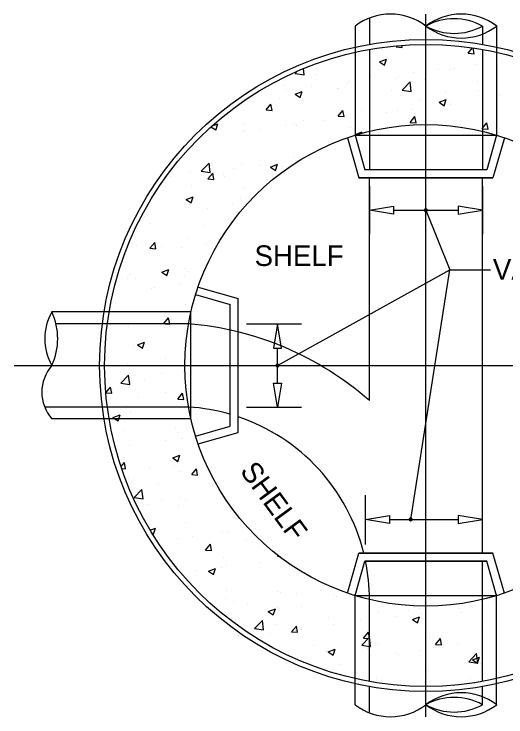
# Model space of a CAD drawing. Extents: x 6712067 to 6713867, y 1867712 to 1869162.
# Drawn here: x 6712515.6 to 6712658.4, y 1867920 to 1868124.2 of the extents above; entities that cross this region are included whole.
import ezdxf

# ---------------------------------------------------------------- set-up
doc = ezdxf.new("R2010")
doc.units = 0
for name, color, linetype in [('G-MARK', 7, 'Continuous'), ('G-TEXT', 7, 'Continuous'), ('Misc CnstDet(22)', 7, 'Continuous')]:
    doc.layers.add(name, color=color, linetype=linetype)

msp = doc.modelspace()

# ---------------------------------------------------------------- linework, layer by layer
at = {"layer": 'G-MARK'}
for p, q in [((6712625.76, 1868067.25), (6712644.59, 1868067.25)), ((6712635.18, 1868067.25), (6712642.18, 1868049.91)), ((6712630.8, 1867977.41), (6712642.18, 1868049.91)), ((6712583.12, 1868034.19), (6712599.1, 1868034.19)), ((6712592.12, 1868017), (6712592.12, 1868027.19)), ((6712583.12, 1868010), (6712599.1, 1868010)), ((6712617.66, 1867970.09), (6712617.66, 1867984.4)), ((6712624.65, 1867977.41), (6712644.59, 1867977.41))]:
    msp.add_line(p, q, dxfattribs=at)
msp.add_lwpolyline([(6712592.12, 1868022.15), (6712642.18, 1868049.91), (6712653.98, 1868049.91)], dxfattribs=at)
at = {"layer": 'G-TEXT'}
for points in [[(6712625.76, 1868068.42), (6712625.76, 1868066.1), (6712618.77, 1868067.25)], [(6712644.59, 1868068.42), (6712644.59, 1868066.1), (6712651.58, 1868067.25)], [(6712590.94, 1868027.19), (6712593.27, 1868027.19), (6712592.12, 1868034.19)], [(6712590.94, 1868017), (6712593.27, 1868017), (6712592.12, 1868010)], [(6712624.65, 1867978.57), (6712624.65, 1867976.24), (6712617.66, 1867977.41)], [(6712644.59, 1867978.57), (6712644.59, 1867976.24), (6712651.58, 1867977.41)]]:
    msp.add_lwpolyline(points, close=True, dxfattribs=at)
at = {"layer": 'Misc CnstDet(22)'}
for p, q in [((6712618.78, 1868123.07), (6712618.78, 1868115.45)), ((6712635.18, 1867920.01), (6712635.18, 1868124.24)), ((6712614.62, 1868120.74), (6712614.62, 1868114.69)), ((6712651.59, 1868120.74), (6712651.59, 1868115.45)), ((6712655.74, 1868120.74), (6712655.74, 1868114.45)), ((6712614.62, 1868114.62), (6712614.62, 1868089.01)), ((6712626.53, 1868114.68), (6712626.86, 1868115.05)), ((6712626.53, 1868114.68), (6712628.28, 1868114.52)), ((6712628.28, 1868114.52), (6712628.16, 1868115.16)), ((6712647.44, 1868112.85), (6712648.77, 1868114.43)), ((6712649.19, 1868112.7), (6712648.87, 1868114.42)), ((6712655.74, 1868114.62), (6712655.74, 1868089.01)), ((6712618.78, 1868113.97), (6712618.78, 1868089.01)), ((6712647.44, 1868112.85), (6712649.19, 1868112.7)), ((6712651.59, 1868113.97), (6712651.59, 1868089.01)), ((6712621.68, 1868110.33), (6712623.72, 1868111.12)), ((6712621.68, 1868110.33), (6712623.13, 1868109.36)), ((6712623.13, 1868109.36), (6712623.72, 1868111.11)), ((6712657.29, 1868110.19), (6712657.29, 1868110.19)), ((6712599.81, 1868106.57), (6712599.6, 1868108.37)), ((6712638.84, 1868108.12), (6712638.84, 1868108.12)), ((6712642.32, 1868108.14), (6712642.32, 1868108.14)), ((6712643.55, 1868108.35), (6712643.55, 1868108.35)), ((6712649.88, 1868109.56), (6712649.88, 1868109.56)), ((6712597.21, 1868106.97), (6712597.84, 1868107.62)), ((6712597.21, 1868106.97), (6712599.81, 1868106.57)), ((6712603.54, 1868106.64), (6712603.54, 1868106.64)), ((6712631.54, 1868107.15), (6712631.54, 1868107.15)), ((6712612.46, 1868104.09), (6712612.46, 1868104.09)), ((6712613.13, 1868104.73), (6712613.13, 1868104.73)), ((6712619.09, 1868105.98), (6712619.09, 1868105.98)), ((6712626.56, 1868105.42), (6712626.56, 1868105.42)), ((6712627.19, 1868105.96), (6712627.19, 1868105.96)), ((6712628.32, 1868102.15), (6712630.6, 1868104.51)), ((6712630.92, 1868101.74), (6712630.6, 1868104.51)), ((6712634.65, 1868105.33), (6712634.65, 1868105.33)), ((6712650.21, 1868104.66), (6712650.21, 1868104.66)), ((6712594.11, 1868103.38), (6712594.11, 1868103.38)), ((6712594.79, 1868102.31), (6712594.79, 1868102.31)), ((6712597.5, 1868102.04), (6712597.5, 1868102.04)), ((6712602.09, 1868103.27), (6712602.09, 1868103.27)), ((6712609.55, 1868102.51), (6712609.55, 1868102.51)), ((6712609.68, 1868102.72), (6712609.68, 1868102.72)), ((6712625.24, 1868102.07), (6712625.24, 1868102.07)), ((6712628.32, 1868102.15), (6712630.92, 1868101.74)), ((6712650.54, 1868101.94), (6712650.54, 1868101.94)), ((6712597.19, 1868100.93), (6712599.22, 1868101.71)), ((6712597.19, 1868100.93), (6712598.64, 1868099.96)), ((6712598.64, 1868099.96), (6712599.22, 1868101.71)), ((6712640.8, 1868101.4), (6712640.8, 1868101.4)), ((6712656.36, 1868100.75), (6712656.36, 1868100.75)), ((6712656.93, 1868100.5), (6712656.93, 1868100.5)), ((6712588.77, 1868096.41), (6712590.17, 1868098.09)), ((6712590.51, 1868096.25), (6712590.17, 1868098.08)), ((6712592.55, 1868099.59), (6712592.55, 1868099.59)), ((6712633.53, 1868099.03), (6712633.53, 1868099.03)), ((6712639.08, 1868098.6), (6712641.12, 1868099.38)), ((6712639.08, 1868098.6), (6712640.52, 1868097.62)), ((6712640.52, 1868097.62), (6712641.12, 1868099.38)), ((6712641.97, 1868098.44), (6712641.97, 1868098.44)), ((6712642.2, 1868098.08), (6712642.2, 1868098.08)), ((6712588.77, 1868096.41), (6712590.51, 1868096.25)), ((6712609.68, 1868094.58), (6712611.08, 1868096.25)), ((6712611.42, 1868094.43), (6712611.08, 1868096.25)), ((6712616.54, 1868096.1), (6712616.54, 1868096.1)), ((6712626.83, 1868096.25), (6712626.83, 1868096.25)), ((6712631.16, 1868096.62), (6712631.16, 1868096.62)), ((6712609.68, 1868094.58), (6712611.42, 1868094.43)), ((6712612.11, 1868094.39), (6712612.11, 1868094.39)), ((6712623.87, 1868095.65), (6712623.87, 1868095.65)), ((6712630.58, 1868092.75), (6712631.98, 1868094.43)), ((6712632.32, 1868092.59), (6712631.98, 1868094.43)), ((6712572.95, 1868091.63), (6712574.73, 1868092.32)), ((6712574.15, 1868090.55), (6712574.73, 1868092.32)), ((6712582.17, 1868092.48), (6712582.17, 1868092.48)), ((6712594.41, 1868091.78), (6712594.41, 1868091.78)), ((6712597.14, 1868092.34), (6712597.14, 1868092.34)), ((6712597.73, 1868091.82), (6712597.73, 1868091.82)), ((6712599.54, 1868093.19), (6712599.54, 1868093.19)), ((6712605.45, 1868093.23), (6712605.45, 1868093.23)), ((6712630.58, 1868092.75), (6712632.33, 1868092.6)), ((6712651.59, 1868091.04), (6712652.89, 1868092.59)), ((6712653.23, 1868090.77), (6712652.89, 1868092.59)), ((6712572.78, 1868091.48), (6712574.15, 1868090.56)), ((6712582.01, 1868090.15), (6712582.01, 1868090.15)), ((6712582.53, 1868090.27), (6712582.53, 1868090.27)), ((6712587.13, 1868090.82), (6712587.13, 1868090.82)), ((6712613.29, 1868091.17), (6712613.29, 1868091.17)), ((6712614.62, 1868089.21), (6712616.63, 1868089.99)), ((6712616.48, 1868089.56), (6712616.63, 1868089.97)), ((6712651.49, 1868090.93), (6712651.59, 1868091.04)), ((6712651.49, 1868090.93), (6712651.59, 1868090.92)), ((6712651.59, 1868090.92), (6712653.23, 1868090.77)), ((6712656.59, 1868090.79), (6712656.59, 1868090.79)), ((6712612.4, 1868088.29), (6712615.72, 1868076.66)), ((6712614.59, 1868089.19), (6712614.62, 1868089.21)), ((6712614.59, 1868089.19), (6712614.62, 1868089.17)), ((6712614.62, 1868089.17), (6712614.78, 1868089.07)), ((6712614.62, 1868089.01), (6712617.48, 1868078.99)), ((6712614.62, 1868089.01), (6712655.74, 1868089.01)), ((6712618.78, 1868089.01), (6712618.78, 1868078.99)), ((6712651.59, 1868089.01), (6712651.59, 1868078.99)), ((6712655.74, 1868089.01), (6712652.88, 1868078.99)), ((6712655.74, 1868089.01), (6712652.88, 1868078.99)), ((6712657.97, 1868088.29), (6712654.64, 1868076.66)), ((6712657.97, 1868088.29), (6712654.64, 1868076.66)), ((6712596.79, 1868082.63), (6712596.79, 1868082.63)), ((6712597.79, 1868081.73), (6712597.79, 1868081.73)), ((6712569.97, 1868078.58), (6712572.24, 1868080.94)), ((6712572.56, 1868078.17), (6712572.24, 1868080.94)), ((6712581.65, 1868080.45), (6712581.65, 1868080.45)), ((6712586.75, 1868080.29), (6712586.75, 1868080.29)), ((6712590.1, 1868079.8), (6712592.13, 1868080.58)), ((6712590.1, 1868079.8), (6712591.54, 1868078.82)), ((6712591.54, 1868078.82), (6712592.13, 1868080.58)), ((6712593.67, 1868080.07), (6712593.67, 1868080.07)), ((6712560.94, 1868078.25), (6712560.94, 1868078.25)), ((6712566.93, 1868078.58), (6712566.93, 1868078.58)), ((6712569.97, 1868078.58), (6712572.56, 1868078.18)), ((6712571.91, 1868076.32), (6712573.31, 1868077.98)), ((6712573.64, 1868076.16), (6712573.31, 1868077.98)), ((6712576.5, 1868077.58), (6712576.5, 1868077.58)), ((6712579.45, 1868079.32), (6712579.45, 1868079.32)), ((6712652.88, 1868078.99), (6712617.48, 1868078.99)), ((6712561.04, 1868076.9), (6712561.04, 1868076.9)), ((6712571.91, 1868076.32), (6712573.64, 1868076.16)), ((6712576.67, 1868077.16), (6712576.67, 1868077.16)), ((6712615.72, 1868076.66), (6712654.64, 1868076.66)), ((6712654.64, 1868076.66), (6712615.72, 1868076.66)), ((6712618.77, 1868076.66), (6712618.77, 1868076.66)), ((6712618.78, 1868011.95), (6712618.78, 1868076.66)), ((6712651.58, 1868076.66), (6712651.58, 1868076.66)), ((6712651.59, 1867967.64), (6712651.59, 1868076.66)), ((6712559.67, 1868074.23), (6712559.67, 1868074.23)), ((6712567.08, 1868074.32), (6712567.08, 1868074.32)), ((6712582.64, 1868073.67), (6712582.64, 1868073.67)), ((6712618.77, 1868074.21), (6712618.77, 1868060.27)), ((6712651.58, 1868074.21), (6712651.58, 1868060.27)), ((6712565.6, 1868070.4), (6712567.64, 1868071.18)), ((6712565.6, 1868070.4), (6712567.05, 1868069.42)), ((6712567.05, 1868069.41), (6712567.64, 1868071.18)), ((6712581.3, 1868070.74), (6712581.3, 1868070.74)), ((6712566.57, 1868068.88), (6712566.57, 1868068.88)), ((6712571.78, 1868067.83), (6712571.78, 1868067.83)), ((6712579.08, 1868068.79), (6712579.08, 1868068.79)), ((6712651.58, 1868067.25), (6712651.58, 1868067.25)), ((6712553.37, 1868065.4), (6712553.37, 1868065.4)), ((6712555.13, 1868063.43), (6712555.13, 1868063.43)), ((6712570.69, 1868062.76), (6712570.69, 1868062.76)), ((6712566.22, 1868059.17), (6712566.22, 1868059.17)), ((6712575.47, 1868059.76), (6712575.47, 1868059.76)), ((6712551.25, 1868057.12), (6712551.25, 1868057.12)), ((6712555.04, 1868056.21), (6712556.45, 1868057.89)), ((6712556.78, 1868056.06), (6712556.45, 1868057.89)), ((6712571.41, 1868057.29), (6712571.41, 1868057.29)), ((6712555.04, 1868056.21), (6712556.78, 1868056.06)), ((6712558.47, 1868056.84), (6712558.47, 1868056.84)), ((6712564.12, 1868056.33), (6712564.12, 1868056.33)), ((6712558.5, 1868049.26), (6712560.55, 1868050.04)), ((6712558.5, 1868049.26), (6712559.96, 1868048.28)), ((6712559.96, 1868048.28), (6712560.55, 1868050.04)), ((6712565.46, 1868050.44), (6712565.46, 1868050.44)), ((6712565.86, 1868049.48), (6712565.86, 1868049.48)), ((6712548.45, 1868047.52), (6712548.45, 1868047.52)), ((6712549.46, 1868048.53), (6712549.46, 1868048.53)), ((6712550.9, 1868047.42), (6712550.9, 1868047.42)), ((6712565.02, 1868047.87), (6712565.02, 1868047.87)), ((6712556.45, 1868044.83), (6712556.45, 1868044.83)), ((6712563.75, 1868045.79), (6712563.75, 1868045.79)), ((6712569.04, 1868044.93), (6712580.68, 1868041.6)), ((6712555.6, 1868044.61), (6712555.6, 1868044.61)), ((6712568.32, 1868042.72), (6712578.35, 1868039.85)), ((6712580.68, 1868002.69), (6712580.68, 1868041.6)), ((6712565.5, 1868039.77), (6712565.5, 1868039.77)), ((6712578.35, 1868004.46), (6712578.35, 1868039.85)), ((6712541.73, 1868037.68), (6712526.6, 1868037.68)), ((6712566.97, 1868037.68), (6712541.73, 1868037.68)), ((6712550.54, 1868037.71), (6712550.54, 1868037.71)), ((6712559.58, 1868037.32), (6712559.58, 1868037.32)), ((6712566.97, 1868006.62), (6712566.97, 1868037.68)), ((6712559.09, 1868034.29), (6712560.49, 1868035.97)), ((6712560.81, 1868034.25), (6712560.49, 1868035.97)), ((6712566.27, 1868034.25), (6712527.77, 1868034.25)), ((6712543.65, 1868033.72), (6712543.65, 1868033.72)), ((6712548.78, 1868033.34), (6712548.78, 1868033.34)), ((6712556.07, 1868034.29), (6712556.07, 1868034.29)), ((6712559.09, 1868034.29), (6712559.55, 1868034.25)), ((6712559.22, 1868033.05), (6712559.22, 1868033.05)), ((6712559.55, 1868034.25), (6712560.82, 1868034.14)), ((6712560.82, 1868034.13), (6712560.81, 1868034.25)), ((6712580.67, 1868034.19), (6712580.67, 1868034.19)), ((6712592.12, 1868034.19), (6712592.12, 1868034.19)), ((6712551.41, 1868028.12), (6712553.45, 1868028.9)), ((6712552.87, 1868027.14), (6712553.45, 1868028.9)), ((6712565.15, 1868030.07), (6712565.15, 1868030.07)), ((6712550.18, 1868028.02), (6712550.18, 1868028.02)), ((6712551.41, 1868028.12), (6712552.87, 1868027.14)), ((6712548.41, 1868022.81), (6712548.41, 1868022.81)), ((6712559.45, 1868024.25), (6712559.45, 1868024.25)), ((6712515.6, 1868022.15), (6712754.77, 1868022.15)), ((6712564.8, 1868020.36), (6712564.8, 1868020.36)), ((6712546.59, 1868016.96), (6712548.86, 1868019.33)), ((6712549.19, 1868016.56), (6712548.86, 1868019.33)), ((6712549.83, 1868018.31), (6712549.83, 1868018.31)), ((6712558.38, 1868019.92), (6712558.38, 1868019.92)), ((6712546.59, 1868016.96), (6712549.19, 1868016.56)), ((6712553.55, 1868018.16), (6712553.55, 1868018.16)), ((6712542.24, 1868014.22), (6712543.63, 1868015.87)), ((6712542.24, 1868014.19), (6712543.96, 1868014.04)), ((6712543.96, 1868014.04), (6712543.63, 1868015.86)), ((6712544.12, 1868014.9), (6712544.12, 1868014.9)), ((6712559.69, 1868014.24), (6712559.69, 1868014.24)), ((6712551.78, 1868012.75), (6712551.78, 1868012.75)), ((6712563.13, 1868012.36), (6712564.54, 1868014.04)), ((6712563.13, 1868012.36), (6712564.87, 1868012.21)), ((6712564.87, 1868012.21), (6712564.53, 1868014.04)), ((6712565.37, 1868013.53), (6712565.37, 1868013.53)), ((6712566.27, 1868010.04), (6712524.49, 1868010.04)), ((6712548.37, 1868010.62), (6712548.37, 1868010.62)), ((6712564.45, 1868010.65), (6712564.45, 1868010.65)), ((6712549.48, 1868008.61), (6712549.48, 1868008.61)), ((6712580.67, 1868010), (6712580.67, 1868010)), ((6712541.73, 1868006.62), (6712526.6, 1868006.62)), ((6712566.97, 1868006.62), (6712541.73, 1868006.62)), ((6712544.32, 1868006.98), (6712546.36, 1868007.77)), ((6712544.32, 1868006.98), (6712544.86, 1868006.62)), ((6712544.86, 1868006.62), (6712545.78, 1868006)), ((6712545.78, 1868006), (6712545.98, 1868006.62)), ((6712545.98, 1868006.62), (6712546.36, 1868007.76)), ((6712568.32, 1868001.59), (6712578.35, 1868004.46)), ((6712547.74, 1868003.34), (6712547.74, 1868003.34)), ((6712562.52, 1868003.69), (6712562.52, 1868003.69)), ((6712563.3, 1868002.69), (6712563.3, 1868002.69)), ((6712569.04, 1867999.36), (6712580.68, 1868002.69)), ((6712559.5, 1868000.42), (6712559.5, 1868000.42)), ((6712564.09, 1868000.95), (6712564.09, 1868000.95)), ((6712549.13, 1867998.9), (6712549.13, 1867998.9)), ((6712561.72, 1867995.25), (6712563.76, 1867996.03)), ((6712563.17, 1867994.26), (6712563.76, 1867996.03)), ((6712546.66, 1867992.74), (6712547.67, 1867993.94)), ((6712548, 1867992.12), (6712547.67, 1867993.94)), ((6712561.72, 1867995.25), (6712563.17, 1867994.26)), ((6712546.83, 1867992.22), (6712548, 1867992.12)), ((6712554.85, 1867992.19), (6712554.85, 1867992.19)), ((6712562.15, 1867993.15), (6712562.15, 1867993.15)), ((6712567.17, 1867990.44), (6712568.58, 1867992.12)), ((6712568.91, 1867990.28), (6712568.58, 1867992.11)), ((6712563.74, 1867991.25), (6712563.74, 1867991.25)), ((6712567.17, 1867990.44), (6712568.91, 1867990.28)), ((6712548.77, 1867989.2), (6712548.77, 1867989.2)), ((6712557.63, 1867987.79), (6712557.63, 1867987.79)), ((6712550.46, 1867983.74), (6712552.73, 1867986.1)), ((6712553.05, 1867983.34), (6712552.72, 1867986.1)), ((6712573.19, 1867987.14), (6712573.19, 1867987.14)), ((6712575.29, 1867985.93), (6712575.29, 1867985.93)), ((6712550.46, 1867983.74), (6712553.05, 1867983.34)), ((6712563.77, 1867983.88), (6712563.77, 1867983.88)), ((6712651.58, 1867977.37), (6712651.58, 1867984.4)), ((6712554.48, 1867981.65), (6712554.48, 1867981.65)), ((6712558.3, 1867983.02), (6712558.3, 1867983.02)), ((6712563.38, 1867981.55), (6712563.38, 1867981.55)), ((6712565.52, 1867983.1), (6712565.52, 1867983.1)), ((6712651.58, 1867977.41), (6712651.58, 1867977.41)), ((6712565.29, 1867976.61), (6712565.29, 1867976.61)), ((6712555.12, 1867974.3), (6712556.67, 1867974.89)), ((6712555.64, 1867973.44), (6712556.08, 1867973.14)), ((6712556.08, 1867973.13), (6712556.67, 1867974.89)), ((6712576.26, 1867974.03), (6712576.26, 1867974.03)), ((6712577.75, 1867973.71), (6712577.75, 1867973.71)), ((6712651.58, 1867974.93), (6712651.58, 1867974.93)), ((6712557.85, 1867971.61), (6712557.85, 1867971.61)), ((6712563.03, 1867971.84), (6712563.03, 1867971.84)), ((6712567.39, 1867972.32), (6712567.39, 1867972.32)), ((6712582.95, 1867971.66), (6712582.95, 1867971.66)), ((6712571.22, 1867968.51), (6712572.62, 1867970.19)), ((6712572.96, 1867968.36), (6712572.62, 1867970.19)), ((6712571.22, 1867968.51), (6712572.96, 1867968.36)), ((6712612.4, 1867956), (6712615.72, 1867967.64)), ((6712612.4, 1867956), (6712615.72, 1867967.64)), ((6712615.72, 1867967.64), (6712654.64, 1867967.64)), ((6712654.64, 1867967.64), (6712615.72, 1867967.64)), ((6712617.66, 1867967.64), (6712617.66, 1867967.64)), ((6712657.97, 1867956), (6712654.64, 1867967.64)), ((6712657.97, 1867956), (6712654.64, 1867967.64)), ((6712576.42, 1867966.42), (6712576.42, 1867966.42)), ((6712592.13, 1867966.69), (6712592.29, 1867966.88)), ((6712592.13, 1867966.69), (6712592.6, 1867966.64)), ((6712592.54, 1867966.19), (6712592.54, 1867966.19)), ((6712614.62, 1867955.28), (6712617.48, 1867965.31)), ((6712614.62, 1867955.28), (6712617.48, 1867965.31)), ((6712617.48, 1867965.31), (6712652.88, 1867965.31)), ((6712652.88, 1867965.31), (6712617.48, 1867965.31)), ((6712651.59, 1867955.28), (6712651.59, 1867965.31)), ((6712655.74, 1867955.28), (6712652.88, 1867965.31)), ((6712655.74, 1867955.28), (6712652.88, 1867965.31)), ((6712572.03, 1867962.37), (6712574.07, 1867963.15)), ((6712573.48, 1867961.4), (6712574.07, 1867963.15)), ((6712575.89, 1867963.5), (6712575.89, 1867963.5)), ((6712577.39, 1867964), (6712577.39, 1867964)), ((6712586.93, 1867964.94), (6712586.93, 1867964.94)), ((6712568.59, 1867962.53), (6712568.59, 1867962.53)), ((6712572.03, 1867962.37), (6712573.48, 1867961.4)), ((6712577.28, 1867956.76), (6712577.28, 1867956.76)), ((6712592.19, 1867956.49), (6712592.19, 1867956.49)), ((6712592.83, 1867956.11), (6712592.83, 1867956.11)), ((6712597.67, 1867955.88), (6712597.67, 1867955.88)), ((6712604.97, 1867956.84), (6712604.97, 1867956.84)), ((6712608.39, 1867955.45), (6712608.39, 1867955.45)), ((6712609.21, 1867954.87), (6712609.21, 1867954.87)), ((6712614.62, 1867923.55), (6712614.62, 1867955.67)), ((6712614.62, 1867955.28), (6712655.74, 1867955.28)), ((6712618.78, 1867930.33), (6712618.78, 1867955.28)), ((6712651.59, 1867930.33), (6712651.59, 1867955.28)), ((6712655.74, 1867923.55), (6712655.74, 1867955.67)), ((6712577.04, 1867954.3), (6712577.04, 1867954.3)), ((6712579.26, 1867953.46), (6712579.26, 1867953.46)), ((6712583.42, 1867952.85), (6712583.42, 1867952.85)), ((6712655.07, 1867953.48), (6712655.07, 1867953.48)), ((6712589.43, 1867950.63), (6712591.47, 1867951.42)), ((6712590.88, 1867949.66), (6712591.47, 1867951.41)), ((6712592.21, 1867951.94), (6712592.21, 1867951.94)), ((6712598.98, 1867952.19), (6712598.98, 1867952.19)), ((6712614.54, 1867951.54), (6712614.54, 1867951.54)), ((6712630.1, 1867950.87), (6712630.1, 1867950.87)), ((6712633.19, 1867951.38), (6712633.19, 1867951.38)), ((6712645.09, 1867951.63), (6712645.09, 1867951.63)), ((6712589.43, 1867950.63), (6712590.88, 1867949.66)), ((6712606.8, 1867948.83), (6712606.8, 1867948.83)), ((6712621.52, 1867950.7), (6712621.52, 1867950.7)), ((6712626.75, 1867949.22), (6712626.75, 1867949.22)), ((6712631.32, 1867948.3), (6712633.36, 1867949.08)), ((6712632.77, 1867947.33), (6712633.36, 1867949.08)), ((6712634.05, 1867950.17), (6712634.05, 1867950.17)), ((6712645.66, 1867950.22), (6712645.66, 1867950.22)), ((6712585.43, 1867945.7), (6712587.7, 1867948.06)), ((6712588.02, 1867945.3), (6712587.7, 1867948.06)), ((6712591.83, 1867946.79), (6712591.83, 1867946.79)), ((6712608.34, 1867946.79), (6712608.34, 1867946.79)), ((6712616.19, 1867948.46), (6712616.19, 1867948.46)), ((6712631.32, 1867948.3), (6712632.77, 1867947.33)), ((6712585.43, 1867945.7), (6712588.02, 1867945.3)), ((6712596.17, 1867944.76), (6712597.58, 1867946.43)), ((6712596.17, 1867944.76), (6712597.91, 1867944.61)), ((6712597.3, 1867945.34), (6712597.3, 1867945.34)), ((6712597.91, 1867944.61), (6712597.58, 1867946.43)), ((6712599.2, 1867945.55), (6712599.2, 1867945.55)), ((6712651.26, 1867945.24), (6712651.26, 1867945.24)), ((6712590.01, 1867944.38), (6712590.01, 1867944.38)), ((6712616.54, 1867940.88), (6712618.78, 1867943.2)), ((6712617.08, 1867942.93), (6712618.48, 1867944.61)), ((6712617.08, 1867942.93), (6712618.78, 1867942.78)), ((6712618.78, 1867943.04), (6712618.48, 1867944.6)), ((6712618.78, 1867943.2), (6712618.81, 1867943.24)), ((6712618.82, 1867942.77), (6712618.78, 1867943.04)), ((6712618.78, 1867942.78), (6712618.82, 1867942.77)), ((6712619.13, 1867940.46), (6712618.81, 1867943.24)), ((6712636.3, 1867943.18), (6712636.3, 1867943.18)), ((6712637.99, 1867941.1), (6712639.39, 1867942.77)), ((6712639.73, 1867940.95), (6712639.39, 1867942.77)), ((6712602.59, 1867940.64), (6712602.59, 1867940.64)), ((6712616.54, 1867940.88), (6712618.78, 1867940.52)), ((6712621.16, 1867941), (6712621.16, 1867941)), ((6712637.99, 1867941.1), (6712639.73, 1867940.95)), ((6712644.32, 1867941.18), (6712644.32, 1867941.18)), ((6712655.83, 1867942.55), (6712655.83, 1867942.55)), ((6712606.44, 1867939.13), (6712606.44, 1867939.13)), ((6712606.83, 1867938.9), (6712608.87, 1867939.68)), ((6712606.83, 1867938.9), (6712608.28, 1867937.93)), ((6712608.28, 1867937.92), (6712608.87, 1867939.68)), ((6712618.16, 1867939.97), (6712618.16, 1867939.97)), ((6712618.78, 1867940.52), (6712619.13, 1867940.46)), ((6712626.37, 1867938.67), (6712626.37, 1867938.67)), ((6712633.72, 1867939.32), (6712633.72, 1867939.32)), ((6712637.41, 1867940.13), (6712637.41, 1867940.13)), ((6712649.28, 1867938.66), (6712649.28, 1867938.66)), ((6712619.09, 1867937.72), (6712619.09, 1867937.72)), ((6712627.33, 1867938.26), (6712627.33, 1867938.26)), ((6712647.65, 1867936.05), (6712649.92, 1867938.41)), ((6712648.72, 1867936.56), (6712650.76, 1867937.35)), ((6712648.72, 1867936.56), (6712650.17, 1867935.59)), ((6712650.24, 1867935.64), (6712649.92, 1867938.41)), ((6712650.16, 1867935.59), (6712650.76, 1867937.34)), ((6712610.33, 1867935.35), (6712610.33, 1867935.35)), ((6712647.65, 1867936.05), (6712650.24, 1867935.64)), ((6712650.91, 1867935.53), (6712650.91, 1867935.53)), ((6712635.94, 1867933.48), (6712635.94, 1867933.48)), ((6712620.81, 1867931.3), (6712620.81, 1867931.3)), ((6712648.15, 1867931.05), (6712648.15, 1867931.05)), ((6712655.45, 1867932.02), (6712655.45, 1867932.02)), ((6712618.78, 1867921.22), (6712618.78, 1867928.85)), ((6712651.59, 1867923.55), (6712651.59, 1867928.85))]:
    msp.add_line(p, q, dxfattribs=at)
for radius in [94.73, 93.28, 69.96]:
    msp.add_circle((6712635.18, 1868022.15), radius, dxfattribs=at)
for centre, radius, start, end in [((6712624.9, 1868107.28), 16.94, 52.6308, 127.3692), ((6712645.46, 1868107.28), 16.94, 52.6308, 127.3692), ((6712643.39, 1868106.02), 16.86, 60.8723, 119.1277), ((6712645.46, 1868134.21), 16.94, 232.6308, 307.3692), ((6712643.39, 1868135.47), 16.86, 240.8723, 299.1277), ((6712635.17, 1868067.25), 0.437, 111.9672, 291.9672), ((6712635.17, 1868067.25), 0.437, 291.9672, 111.9672), ((6712539.81, 1868029.91), 15.32, 149.5444, 210.4556), ((6712509.46, 1868029.91), 18.82, 335.6342, 24.3658), ((6712558.8, 1867943.73), 90.82, 48.68, 85.2791), ((6712592.12, 1868022.15), 0.437, 29.0121, 209.0121), ((6712592.12, 1868022.15), 0.437, 209.0121, 29.0121), ((6712535.37, 1868014.38), 11.71, 138.4565, 221.5435), ((6712562.78, 1867954.15), 56.01, 73.864, 86.4141), ((6712562.78, 1867954.15), 56.01, 13.9377, 71.364), ((6712630.8, 1867977.41), 0.437, 81.0895, 261.0895), ((6712630.8, 1867977.41), 0.437, 261.0895, 81.0895), ((6712562.78, 1867954.15), 56.01, 359.9903, 11.492), ((6712645.46, 1867910.09), 16.94, 52.6308, 127.3692), ((6712643.39, 1867908.83), 16.86, 60.8723, 119.1277), ((6712624.9, 1867937.02), 16.94, 232.6308, 307.3692), ((6712645.46, 1867937.02), 16.94, 232.6308, 307.3692), ((6712643.39, 1867938.28), 16.86, 240.8723, 299.1277)]:
    msp.add_arc(centre, radius, start, end, dxfattribs=at)

# ---------------------------------------------------------------- texts
for s, p in [('SHELF', (6712585.43, 1868051.03)), ('VARIABLE', (6712654.65, 1868047.04))]:
    msp.add_text(s, height=6, dxfattribs=at).set_placement(p)
msp.add_text('SHELF', height=6, rotation=306.2842, dxfattribs=at).set_placement((6712581.01, 1867991.39))

doc.saveas('drawing.dxf')
